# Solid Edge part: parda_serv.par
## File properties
Author: Blackblade
Template: Normal.par
Last saved by: Blackblade
Revision: 3
Application: Solid Edge
Accuracy: 0.990
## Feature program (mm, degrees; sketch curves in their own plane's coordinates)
sketch for "unnamed Protrusion 1" plane through (50.4805, -11.3038, 0) normal (0, 0, 1) x-axis (1, 0, 0)
  arc centre (49.919, -577.1273) radius 650 from (234.7252, 46.0474) to (-249.1196, 0) ccw
  arc centre (49.919, 577.1273) radius 650 from (234.7252, -46.0474) to (-249.1196, 0) cw
  arc centre (168.2704, 0) radius 80.8492 from (234.7252, -46.0474) to (234.7252, 46.0474) ccw
extrude "unnamed Protrusion 1" add finite 10 along +normal
sketch for "unnamed Cutout 1" plane through (0, 0, 0) normal (0, 0, 1) x-axis (1, 0, 0)
  arc centre (100.3995, -588.4311) radius 649 from (284.583, 33.8851) to (-196.4592, -11.3038) ccw
  arc centre (100.3995, 565.8235) radius 649 from (-196.4592, -11.3038) to (284.583, -56.4927) ccw
  arc centre (218.751, -11.3038) radius 79.8492 from (284.583, -56.4927) to (284.583, 33.8851) ccw
extrude "unnamed Cutout 1" cut to key point along +normal
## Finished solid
Body 1: solid body, 8 faces, 18 edges, 12 vertices.
  Faces by surface: cylinder 6, plane 2
  Edges by curve: circle 12, line 6
Bounding box of the edges (mm): 498.239 x 145.745 x 10.000, from (-198.6391, -84.1765, 0) to (299.6002, 61.5689, 10).
Cylindrical faces by radius (mm): R79.8492 x1, R80.8492 x1, R649 x2, R650 x2
Planar faces by outward normal: +z 1, -z 1
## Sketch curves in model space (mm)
arc centre (100.3995, 565.8235, 0) radius 649 from (-196.4592, -11.3038, 0) through (39.7, -80.3318, 0) to (284.583, -56.4927, 0)
arc centre (218.751, -11.3038, 0) radius 79.8492 from (284.583, -56.4927, 0) through (298.5674, -9.0168, 0) to (284.583, 33.8851, 0)
arc centre (100.3995, -588.4311, 0) radius 649 from (284.583, 33.8851, 0) through (39.7, 57.7241, 0) to (-196.4592, -11.3038, 0)
arc centre (100.3995, 565.8235, 0) radius 650 from (285.2057, -57.3512, 0) through (38.8175, -81.2528, 0) to (-198.6391, -11.3038, 0)
arc centre (218.751, -11.3038, 0) radius 80.8492 from (285.2057, -57.3512, 0) through (299.5665, -8.9713, 0) to (285.2057, 34.7435, 0)
arc centre (100.3995, -588.4311, 0) radius 650 from (285.2057, 34.7435, 0) through (38.8175, 58.6451, 0) to (-198.6391, -11.3038, 0)
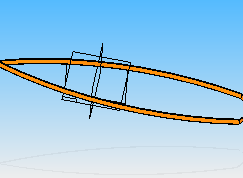
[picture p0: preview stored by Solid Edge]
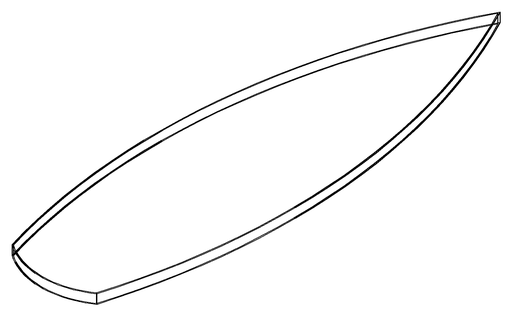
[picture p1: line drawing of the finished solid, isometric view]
